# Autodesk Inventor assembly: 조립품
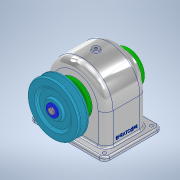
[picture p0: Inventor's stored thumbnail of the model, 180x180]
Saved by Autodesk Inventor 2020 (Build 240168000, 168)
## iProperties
Created: 2022-09
Part Number: 조립품
Document SubType Name: Assembly
Designer: USER
Author: USER
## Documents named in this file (16)
- C:\Users\USER\Desktop\720906V1002\조립품.iam
- C:\Users\USER\Desktop\720906V1002\본체.ipt
- C:\Users\USER\Desktop\720906V1002\V-벨트풀리.ipt
- C:\Users\USER\Desktop\720906V1002\뒤커버.ipt
- C:\Users\USER\Desktop\720906V1002\멈춤나사 M4 x 10.ipt
- C:\Users\USER\Desktop\720906V1002\베어링 6203.ipt
- C:\Users\USER\Desktop\720906V1002\볼트 M3 x 10.ipt
- C:\Users\USER\Desktop\720906V1002\스퍼기어.ipt
- C:\Users\USER\Desktop\720906V1002\앞커버.ipt
- C:\Users\USER\Desktop\720906V1002\오일 실 17 x 30 x 8.ipt
- C:\Users\USER\Desktop\720906V1002\와셔 6 x 22.ipt
- C:\Users\USER\Desktop\720906V1002\육각머리볼트 M3 x 8.ipt
- C:\Users\USER\Desktop\720906V1002\축.ipt
- C:\Users\USER\Desktop\720906V1002\칼라.ipt
- C:\Users\USER\Desktop\720906V1002\키 5 x 5 x 18.ipt
- C:\Users\USER\Desktop\720906V1002\키 6 x 6 x 22.ipt
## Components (9 placed, 2 different names)
1. V-벨트풀리:1
2. ISO 4762 M3 x 10:1
3. ISO 4762 M3 x 10:2
4. ISO 4762 M3 x 10:3
5. ISO 4762 M3 x 10:4
6. ISO 4762 M3 x 10:5
7. ISO 4762 M3 x 10:6
8. ISO 4762 M3 x 10:7
9. ISO 4762 M3 x 10:8
